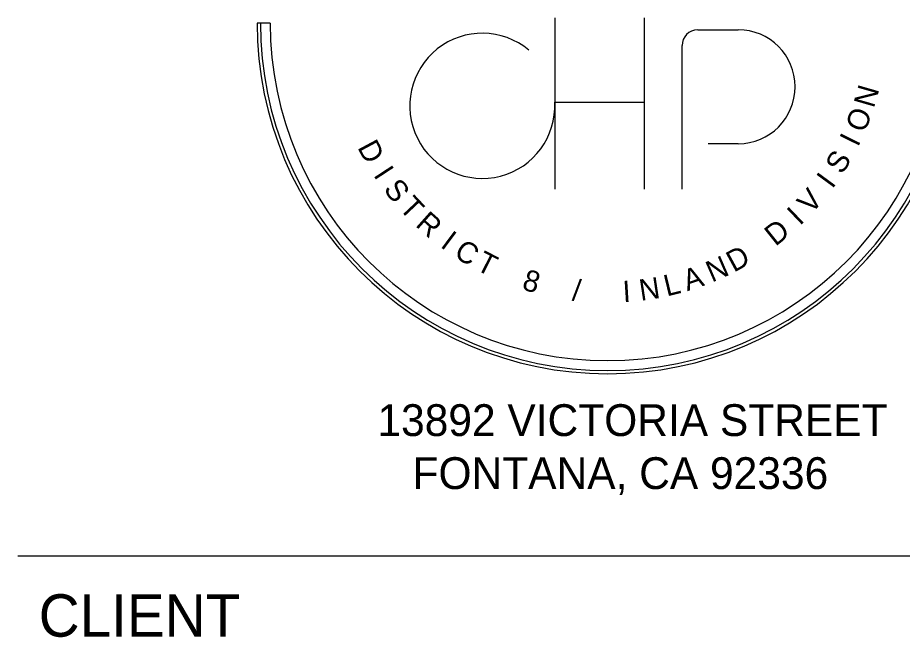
# Model space of a CAD drawing. Extents: x 0 to 3.5, y -0.08 to 2.5.
# Drawn here: x 3.1667 to 3.3841, y 2.1745 to 2.3267 of the extents above; entities that cross this region are included whole.
import ezdxf

# ---------------------------------------------------------------- set-up
doc = ezdxf.new("R2010")
doc.units = 0
for name, color, linetype in [('A-ANNO-TEXT', 7, 'Continuous'), ('Default', 7, 'Continuous'), ('G-ANNO-TTLB', 7, 'Continuous')]:
    doc.layers.add(name, color=color, linetype=linetype)

msp = doc.modelspace()

# ---------------------------------------------------------------- linework, layer by layer
at = {"layer": 'A-ANNO-TEXT'}
for p, q in [((3.2287457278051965, 2.3254449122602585), (3.225519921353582, 2.3254449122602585)), ((3.298693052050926, 2.326747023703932), (3.298693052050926, 2.284657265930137)), ((3.3207178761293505, 2.326747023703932), (3.3207178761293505, 2.284657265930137))]:
    msp.add_line(p, q, dxfattribs=at)
for points in [[(3.3338532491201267, 2.3237780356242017), (3.3437915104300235, 2.3237780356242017)], [(3.3299822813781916, 2.284657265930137), (3.3299822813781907, 2.3199070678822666)], [(3.298693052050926, 2.3059641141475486), (3.3207178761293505, 2.305964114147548)], [(3.3437915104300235, 2.2957933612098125), (3.3364018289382, 2.2957933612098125)]]:
    msp.add_lwpolyline(points, dxfattribs=at)
for centre, radius, start, end in [((3.3116927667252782, 2.3254449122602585), 0.08617284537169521, 180, 0), ((3.3116927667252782, 2.3254449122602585), 0.085366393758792, 180, 0), ((3.3116927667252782, 2.3254449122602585), 0.08294703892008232, 180, 0), ((3.2808848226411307, 2.3050908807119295), 0.017829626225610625, 50.1687457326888, 2.8072722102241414), ((3.333853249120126, 2.3199070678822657), 0.0038709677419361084, 89.99999999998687, 179.99999999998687), ((3.3437915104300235, 2.309785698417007), 0.013992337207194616, 270, 90)]:
    msp.add_arc(centre, radius, start, end, dxfattribs=at)
at = {"layer": 'G-ANNO-TTLB'}
msp.add_lwpolyline([(3.1666666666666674, 2.1945492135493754), (3.458333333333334, 2.1945492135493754)], dxfattribs=at)

# ---------------------------------------------------------------- texts
at = {"layer": 'Default'}
for s, height, rotation, p in [('N', 0.00523625, 73.85759863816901, (3.3771357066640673, 2.3043582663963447)), ('O', 0.00523625, 68.83244079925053, (3.3748773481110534, 2.298294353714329)), ('D', 0.005236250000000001, 298.17833698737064, (3.25009136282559, 2.2948978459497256)), ('I', 0.005236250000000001, 63.8072829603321, (3.3732085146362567, 2.294799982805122)), ('S', 0.0052362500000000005, 58.78212512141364, (3.3693894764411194, 2.2880471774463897)), ('I', 0.005236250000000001, 303.2034948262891, (3.2539988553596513, 2.2880990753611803)), ('I', 0.005236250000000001, 53.75696728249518, (3.3669166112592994, 2.2845349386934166)), ('S', 0.005236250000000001, 308.22865266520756, (3.2564193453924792, 2.284550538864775)), ('V', 0.005236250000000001, 48.73180944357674, (3.3617704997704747, 2.2783160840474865)), ('T', 0.005236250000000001, 313.253810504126, (3.26021745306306, 2.279862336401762)), ('R', 0.0052362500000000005, 318.2789683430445, (3.264238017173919, 2.275680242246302)), ('I', 0.005236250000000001, 43.70665160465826, (3.3589298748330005, 2.275525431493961)), ('D', 0.005236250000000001, 38.68149376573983, (3.352957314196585, 2.2704440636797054)), ('I', 0.005236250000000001, 323.30412618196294, (3.2703476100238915, 2.2705461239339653)), ('C', 0.005236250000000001, 328.3292840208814, (3.273641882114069, 2.268167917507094)), ('T', 0.0052362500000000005, 333.35444185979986, (3.2790181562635, 2.264948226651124)), ('N', 0.005236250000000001, 23.60602024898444, (3.3373254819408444, 2.261645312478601)), ('D', 0.0052362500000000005, 28.631178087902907, (3.3427257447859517, 2.2640868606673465)), ('8', 0.005236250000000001, 343.4047575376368, (3.290413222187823, 2.2600742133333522)), ('A', 0.005236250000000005, 18.58086241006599, (3.3312712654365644, 2.25952181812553)), ('/', 0.005236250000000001, 353.4550732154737, (3.302847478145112, 2.2572835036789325)), ('I', 0.0052362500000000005, 3.5053888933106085, (3.315549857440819, 2.2568269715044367)), ('N', 0.0052362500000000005, 8.530546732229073, (3.3198495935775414, 2.2571741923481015)), ('L', 0.0052362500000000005, 13.555704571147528, (3.326213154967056, 2.258251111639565))]:
    msp.add_text(s, height=height, rotation=rotation, dxfattribs=at).set_placement(p)
at = {"layer": 'G-ANNO-TTLB'}
for s, height, p in [('13892 VICTORIA STREET', 0.0078125, (3.2551049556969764, 2.2239703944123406)), ('FONTANA, CA 92336', 0.0078125, (3.263735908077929, 2.210949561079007)), ('CLIENT', 0.010416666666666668, (3.1718334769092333, 2.1746730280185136))]:
    msp.add_text(s, height=height, dxfattribs=at).set_placement(p)

doc.saveas('drawing.dxf')
